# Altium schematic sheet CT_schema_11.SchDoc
size 146 x 119 mm
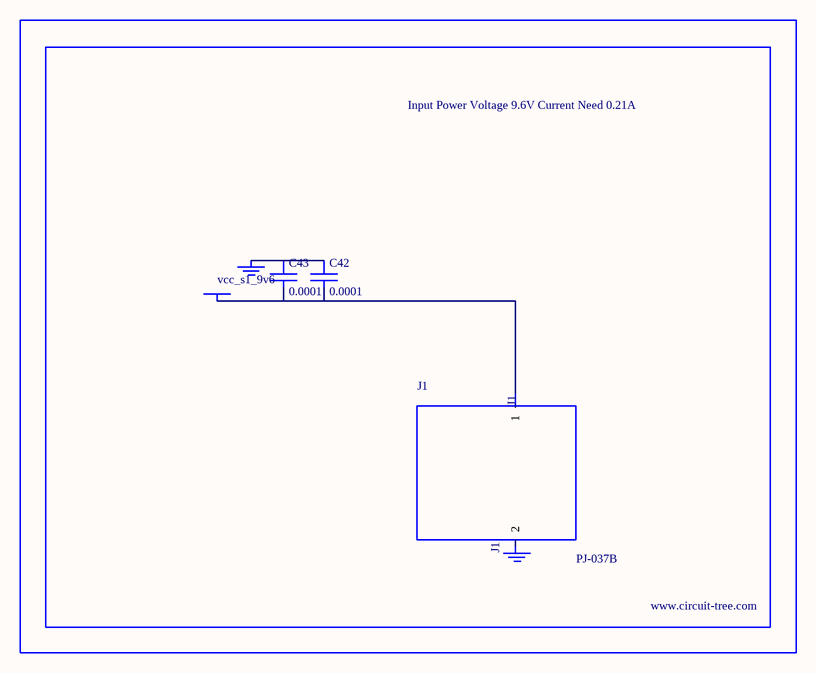
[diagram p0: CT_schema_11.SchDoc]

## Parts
BORDER10  (no value)
C42  0.0001  [EXV-9H]
C43  0.0001  [EXV-9H]
GND_INSTANCE_10_0  (no value)
GND_INSTANCE_10_1  (no value)
J1  PJ-037B  [PJ-037B_PACKAGE]
POWER_INSTANCE_10_0  vcc_s1_9v6

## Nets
NetC42_1: C42.1 C43.1 GND_INSTANCE_10_0.0(GND)
NetC42_2: C42.2 C43.2 J1.1 POWER_INSTANCE_10_0.0(PWR)

Not connected (* = marked no-connect by the designer): GND_INSTANCE_10_1 0(GND); J1 2

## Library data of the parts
BORDER10 = BORDER_PAGE10
C42 C43 = EDK107M035A9HAA
GND_INSTANCE_10_0 GND_INSTANCE_10_1 = GND
POWER_INSTANCE_10_0 = PWR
